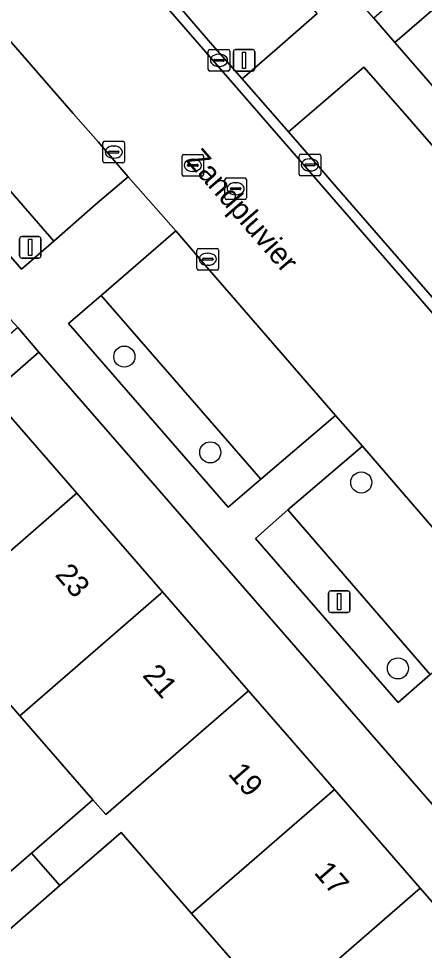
# Model space of a CAD drawing. Extents: x 155887 to 156869, y 383880 to 384678.
# Drawn here: x 156610.61 to 156629.4, y 384018.22 to 384061.4 of the extents above; entities that cross this region are included whole.
import ezdxf

# ---------------------------------------------------------------- set-up
doc = ezdxf.new("R2010")
doc.units = 0
for name, color, linetype in [('IMGEO_Berm_groen', 7, 'Continuous'), ('IMGEO_Boom', 7, 'Continuous'), ('IMGEO_Erf', 7, 'Continuous'), ('IMGEO_Kolk', 7, 'Continuous'), ('IMGEO_Lichtmast', 7, 'Continuous'), ('IMGEO_Openbare_ruimte_label', 7, 'Continuous'), ('IMGEO_Pand', 7, 'Continuous'), ('IMGEO_Pand_nummerreeks', 7, 'Continuous'), ('IMGEO_Parkeervlak_open', 7, 'Continuous'), ('IMGEO_Rijbaan_lokaal_gesloten', 7, 'Continuous'), ('IMGEO_Rijbaan_lokaal_open', 7, 'Continuous'), ('IMGEO_Rioolput', 7, 'Continuous'), ('IMGEO_Voetpad_open', 7, 'Continuous')]:
    doc.layers.add(name, color=color, linetype=linetype)

msp = doc.modelspace()

# ---------------------------------------------------------------- linework, layer by layer
at = {"layer": 'IMGEO_Berm_groen'}
for points in [[(156604.722, 384059.704), (156603.227, 384058.448), (156610.737, 384049.787), (156612.242, 384051.077), (156609.695, 384053.999)], [(156614.431, 384048.566), (156612.922, 384047.266), (156620.318, 384038.756), (156621.82, 384040.051)], [(156623.074, 384038.632), (156621.574, 384037.301), (156628.184, 384029.703), (156629.666, 384031.006)]]:
    msp.add_lwpolyline(points, close=True, dxfattribs=at)
at = {"layer": 'IMGEO_Boom'}
for centre in [(156615.503, 384045.734), (156619.481, 384041.297), (156626.475, 384039.902), (156628.172, 384031.286)]:
    msp.add_circle(centre, 0.489, dxfattribs=at)
at = {"layer": 'IMGEO_Erf'}
for points in [[(156646.204, 384043.928), (156642.223, 384048.506), (156638.243, 384053.084), (156634.262, 384057.662), (156630.286, 384062.235), (156628.032, 384060.288), (156663.829, 384019.095), (156666.095, 384021.051), (156662.126, 384025.616), (156658.145, 384030.194), (156654.165, 384034.772), (156650.184, 384039.35)], [(156611.545, 384045.94), (156609.299, 384043.999), (156613.295, 384039.404), (156617.274, 384034.828), (156621.253, 384030.252), (156625.232, 384025.676), (156629.21, 384021.101), (156633.189, 384016.525), (156637.168, 384011.949), (156641.147, 384007.374), (156645.116, 384002.809), (156647.359, 384004.761)]]:
    msp.add_lwpolyline(points, close=True, dxfattribs=at)
for points in [[(156608.366, 384020.267), (156611.204, 384022.731), (156614.042, 384025.196), (156610.665, 384029.085), (156607.487, 384032.745)], [(156621.909, 384016.138), (156618.616, 384019.93), (156615.353, 384023.687), (156612.515, 384021.222), (156609.677, 384018.757)]]:
    msp.add_lwpolyline(points, dxfattribs=at)
at = {"layer": 'IMGEO_Kolk'}
for p, q in [((156619.385, 384059.038), (156619.385, 384059.89)), ((156619.46, 384059.964), (156620.312, 384059.964)), ((156620.386, 384059.89), (156620.386, 384059.038)), ((156619.644, 384059.458), (156619.644, 384059.47)), ((156620.082, 384059.421), (156619.684, 384059.421)), ((156619.687, 384059.507), (156620.085, 384059.507)), ((156619.873, 384059.744), (156619.898, 384059.744)), ((156620.128, 384059.47), (156620.128, 384059.458)), ((156620.312, 384058.964), (156619.46, 384058.964)), ((156619.896, 384059.184), (156619.871, 384059.184)), ((156614.511, 384054.784), (156614.511, 384055.636)), ((156614.586, 384055.71), (156615.438, 384055.71)), ((156614.999, 384055.49), (156615.024, 384055.49)), ((156615.512, 384055.636), (156615.512, 384054.784)), ((156614.77, 384055.204), (156614.77, 384055.216)), ((156615.208, 384055.167), (156614.81, 384055.167)), ((156614.813, 384055.253), (156615.211, 384055.253)), ((156615.254, 384055.216), (156615.254, 384055.204)), ((156623.597, 384054.192), (156623.597, 384055.044)), ((156623.672, 384055.118), (156624.524, 384055.118)), ((156624.598, 384055.044), (156624.598, 384054.192)), ((156615.438, 384054.71), (156614.586, 384054.71)), ((156615.022, 384054.93), (156614.997, 384054.93)), ((156623.856, 384054.612), (156623.856, 384054.624)), ((156623.899, 384054.661), (156624.297, 384054.661)), ((156624.085, 384054.898), (156624.11, 384054.898)), ((156624.34, 384054.624), (156624.34, 384054.612)), ((156624.294, 384054.575), (156623.896, 384054.575)), ((156624.108, 384054.338), (156624.083, 384054.338)), ((156624.524, 384054.118), (156623.672, 384054.118)), ((156618.942, 384050.746), (156619.794, 384050.746)), ((156618.867, 384049.82), (156618.867, 384050.672)), ((156619.169, 384050.289), (156619.567, 384050.289)), ((156619.355, 384050.526), (156619.38, 384050.526)), ((156619.868, 384050.672), (156619.868, 384049.82)), ((156619.126, 384050.24), (156619.126, 384050.252)), ((156619.564, 384050.203), (156619.166, 384050.203)), ((156619.378, 384049.966), (156619.353, 384049.966)), ((156619.61, 384050.252), (156619.61, 384050.24)), ((156619.794, 384049.746), (156618.942, 384049.746))]:
    msp.add_line(p, q, dxfattribs=at)
for points in [[(156619.385, 384059.038), (156619.385, 384059.89)], [(156619.46, 384059.964), (156620.312, 384059.964)], [(156620.386, 384059.89), (156620.386, 384059.038)], [(156620.312, 384058.964), (156619.46, 384058.964)], [(156614.511, 384054.784), (156614.511, 384055.636)], [(156614.586, 384055.71), (156615.438, 384055.71)], [(156615.512, 384055.636), (156615.512, 384054.784)], [(156623.597, 384054.192), (156623.597, 384055.044)], [(156623.672, 384055.118), (156624.524, 384055.118)], [(156624.598, 384055.044), (156624.598, 384054.192)], [(156615.438, 384054.71), (156614.586, 384054.71)], [(156624.524, 384054.118), (156623.672, 384054.118)], [(156618.942, 384050.746), (156619.794, 384050.746)], [(156618.867, 384049.82), (156618.867, 384050.672)], [(156619.868, 384050.672), (156619.868, 384049.82)], [(156619.794, 384049.746), (156618.942, 384049.746)]]:
    msp.add_lwpolyline(points, dxfattribs=at)
for centre, radius, start, end in [((156619.462, 384059.888), 0.0765, 91.552, 178.448), ((156619.462, 384059.888), 0.0765, 91.552, 178.448), ((156620.31, 384059.888), 0.0765, 1.552, 88.448), ((156620.31, 384059.888), 0.0765, 1.552, 88.448), ((156619.684, 384059.467), 0.0403, 85.8775, 175.7526), ((156619.681, 384059.457), 0.0366, 178.938, 274.7102), ((156620.085, 384059.464), 0.043, 264.8664, 352.4533), ((156620.089, 384059.469), 0.0386, 1.7309, 96.639), ((156619.462, 384059.04), 0.0765, 181.552, 268.448), ((156619.462, 384059.04), 0.0765, 181.552, 268.448), ((156620.31, 384059.04), 0.0765, 271.552, 358.448), ((156620.31, 384059.04), 0.0765, 271.552, 358.448), ((156614.588, 384055.634), 0.0765, 91.552, 178.448), ((156614.588, 384055.634), 0.0765, 91.552, 178.448), ((156615.436, 384055.634), 0.0765, 1.552, 88.448), ((156615.436, 384055.634), 0.0765, 1.552, 88.448), ((156614.81, 384055.213), 0.0403, 85.8775, 175.7526), ((156614.807, 384055.203), 0.0366, 178.938, 274.7102), ((156615.211, 384055.21), 0.043, 264.8664, 352.4533), ((156615.215, 384055.215), 0.0386, 1.7309, 96.639), ((156623.674, 384055.042), 0.0765, 91.552, 178.448), ((156623.674, 384055.042), 0.0765, 91.552, 178.448), ((156624.522, 384055.042), 0.0765, 1.552, 88.448), ((156624.522, 384055.042), 0.0765, 1.552, 88.448), ((156614.588, 384054.786), 0.0765, 181.552, 268.448), ((156614.588, 384054.786), 0.0765, 181.552, 268.448), ((156615.436, 384054.786), 0.0765, 271.552, 358.448), ((156615.436, 384054.786), 0.0765, 271.552, 358.448), ((156623.896, 384054.621), 0.0403, 85.8775, 175.7526), ((156623.893, 384054.611), 0.0366, 178.938, 274.7102), ((156624.297, 384054.618), 0.043, 264.8664, 352.4533), ((156624.301, 384054.623), 0.0386, 1.7309, 96.639), ((156623.674, 384054.194), 0.0765, 181.552, 268.448), ((156623.674, 384054.194), 0.0765, 181.552, 268.448), ((156624.522, 384054.194), 0.0765, 271.552, 358.448), ((156624.522, 384054.194), 0.0765, 271.552, 358.448), ((156618.944, 384050.67), 0.0765, 91.552, 178.448), ((156618.944, 384050.67), 0.0765, 91.552, 178.448), ((156619.792, 384050.67), 0.0765, 1.552, 88.448), ((156619.792, 384050.67), 0.0765, 1.552, 88.448), ((156619.166, 384050.249), 0.0403, 85.8775, 175.7526), ((156619.571, 384050.251), 0.0386, 1.7309, 96.639), ((156619.163, 384050.239), 0.0366, 178.938, 274.7102), ((156619.567, 384050.246), 0.043, 264.8664, 352.4533), ((156618.944, 384049.822), 0.0765, 181.552, 268.448), ((156618.944, 384049.822), 0.0765, 181.552, 268.448), ((156619.792, 384049.822), 0.0765, 271.552, 358.448), ((156619.792, 384049.822), 0.0765, 271.552, 358.448)]:
    msp.add_arc(centre, radius, start, end, dxfattribs=at)
for centre, major_axis, ratio, start_param, end_param in [((156619.872, 384059.464), (-0.387, 0.002), 0.722429, 4.712389, 7.853982), ((156619.897, 384059.464), (-0.39, 0.002), 0.717154, 1.570796, 4.712389), ((156614.998, 384055.21), (-0.387, 0.002), 0.722429, 4.712389, 7.853982), ((156615.023, 384055.21), (-0.39, 0.002), 0.717154, 1.570796, 4.712389), ((156624.084, 384054.618), (-0.387, 0.002), 0.722429, 4.712389, 7.853982), ((156624.109, 384054.618), (-0.39, 0.002), 0.717154, 1.570796, 4.712389), ((156619.354, 384050.246), (-0.387, 0.002), 0.722429, 4.712389, 7.853982), ((156619.379, 384050.246), (-0.39, 0.002), 0.717154, 1.570796, 4.712389)]:
    msp.add_ellipse(centre, major_axis=major_axis, ratio=ratio, start_param=start_param, end_param=end_param, dxfattribs=at)
at = {"layer": 'IMGEO_Lichtmast'}
for p, q in [((156620.551, 384059.063), (156620.551, 384059.863)), ((156620.551, 384059.863), (156620.551, 384059.063)), ((156620.651, 384059.963), (156621.441, 384059.963)), ((156621.441, 384059.963), (156620.651, 384059.963)), ((156621.541, 384059.863), (156621.541, 384059.063)), ((156621.541, 384059.063), (156621.541, 384059.863)), ((156621.441, 384058.963), (156620.651, 384058.963)), ((156620.651, 384058.963), (156621.441, 384058.963)), ((156610.648, 384050.398), (156610.648, 384051.198)), ((156610.648, 384051.198), (156610.648, 384050.398)), ((156610.748, 384051.298), (156611.538, 384051.298)), ((156611.538, 384051.298), (156610.748, 384051.298)), ((156611.638, 384051.198), (156611.638, 384050.398)), ((156611.638, 384050.398), (156611.638, 384051.198)), ((156611.538, 384050.298), (156610.748, 384050.298)), ((156610.748, 384050.298), (156611.538, 384050.298)), ((156624.96, 384033.977), (156624.96, 384034.777)), ((156624.96, 384034.777), (156624.96, 384033.977)), ((156625.06, 384034.877), (156625.85, 384034.877)), ((156625.85, 384034.877), (156625.06, 384034.877)), ((156625.95, 384034.777), (156625.95, 384033.977)), ((156625.95, 384033.977), (156625.95, 384034.777)), ((156625.85, 384033.877), (156625.06, 384033.877)), ((156625.06, 384033.877), (156625.85, 384033.877))]:
    msp.add_line(p, q, dxfattribs=at)
for points in [[(156620.971, 384059.838), (156621.121, 384059.838), (156621.121, 384059.088), (156620.971, 384059.088), (156620.971, 384059.838)], [(156611.068, 384051.173), (156611.218, 384051.173), (156611.218, 384050.423), (156611.068, 384050.423), (156611.068, 384051.173)], [(156625.38, 384034.752), (156625.53, 384034.752), (156625.53, 384034.002), (156625.38, 384034.002), (156625.38, 384034.752)]]:
    msp.add_lwpolyline(points, dxfattribs=at)
for centre, start, end in [((156620.651, 384059.863), 90, 180), ((156620.651, 384059.863), 90, 180), ((156621.441, 384059.863), 0, 90), ((156621.441, 384059.863), 360, 90), ((156620.651, 384059.063), 180, 270), ((156620.651, 384059.063), 180, 270), ((156621.441, 384059.063), 270, 0), ((156621.441, 384059.063), 270, 0), ((156610.748, 384051.198), 90, 180), ((156610.748, 384051.198), 90, 180), ((156611.538, 384051.198), 0, 90), ((156611.538, 384051.198), 360, 90), ((156610.748, 384050.398), 180, 270), ((156610.748, 384050.398), 180, 270), ((156611.538, 384050.398), 270, 0), ((156611.538, 384050.398), 270, 0), ((156625.06, 384034.777), 90, 180), ((156625.06, 384034.777), 90, 180), ((156625.85, 384034.777), 0, 90), ((156625.85, 384034.777), 360, 90), ((156625.06, 384033.977), 180, 270), ((156625.06, 384033.977), 180, 270), ((156625.85, 384033.977), 270, 0), ((156625.85, 384033.977), 270, 0)]:
    msp.add_arc(centre, 0.1, start, end, dxfattribs=at)
at = {"layer": 'IMGEO_Pand'}
for points in [[(156613.205, 384039.325), (156613.295, 384039.404), (156609.299, 384043.999), (156602.674, 384038.239), (156606.176, 384034.255), (156606.689, 384033.664)], [(156617.196, 384034.76), (156617.274, 384034.828), (156613.295, 384039.404), (156613.205, 384039.325), (156606.689, 384033.664), (156606.176, 384034.255), (156603.337, 384031.79), (156604.648, 384030.28), (156607.487, 384032.745), (156610.665, 384029.085)], [(156621.253, 384030.252), (156617.274, 384034.828), (156617.196, 384034.76), (156610.665, 384029.085), (156614.042, 384025.196), (156614.64, 384024.508)], [(156625.232, 384025.676), (156621.253, 384030.252), (156614.64, 384024.508), (156614.042, 384025.196), (156611.204, 384022.731), (156612.515, 384021.222), (156615.353, 384023.687), (156618.616, 384019.93)], [(156629.21, 384021.101), (156625.232, 384025.676), (156618.616, 384019.93), (156621.909, 384016.138), (156622.592, 384015.351)], [(156612.515, 384021.222), (156611.204, 384022.731), (156608.366, 384020.267), (156608.964, 384019.578), (156609.677, 384018.757)], [(156633.189, 384016.525), (156629.21, 384021.101), (156622.592, 384015.351), (156621.909, 384016.138), (156619.07, 384013.673), (156620.382, 384012.163), (156623.22, 384014.628), (156626.568, 384010.773)]]:
    msp.add_lwpolyline(points, close=True, dxfattribs=at)
at = {"layer": 'IMGEO_Parkeervlak_open'}
for points in [[(156616.904, 384070.314), (156613.441, 384067.288), (156618.345, 384061.609), (156619.483, 384060.292), (156620.955, 384058.609), (156622.581, 384060.015), (156624.428, 384061.64), (156621.832, 384064.636)], [(156608.204, 384062.662), (156604.722, 384059.704), (156609.695, 384053.999), (156612.242, 384051.077), (156614.168, 384052.776), (156615.678, 384054.06), (156614.29, 384055.679), (156613.133, 384057.006)], [(156628.486, 384056.983), (156626.59, 384059.141), (156624.722, 384057.535), (156623.112, 384056.157), (156624.566, 384054.471), (156625.01, 384053.951), (156634.535, 384043.005), (156638.005, 384046.033)], [(156619.335, 384049.866), (156617.88, 384051.561), (156616.264, 384050.155), (156614.431, 384048.566), (156621.82, 384040.051), (156625.284, 384043.011)], [(156623.074, 384038.632), (156629.666, 384031.006), (156633.113, 384033.952), (156626.529, 384041.587)]]:
    msp.add_lwpolyline(points, close=True, dxfattribs=at)
at = {"layer": 'IMGEO_Rijbaan_lokaal_gesloten'}
msp.add_lwpolyline([(156646.454, 384028.54), (156584.127, 384100.331), (156579.597, 384096.394), (156579.244, 384096.079), (156582.931, 384091.822), (156583.811, 384090.821), (156585.156, 384089.249), (156586.193, 384088.05), (156591.142, 384082.341), (156592.38, 384080.913), (156599, 384073.239), (156600.266, 384071.831), (156606.948, 384064.118), (156608.204, 384062.662), (156613.133, 384057.006), (156614.29, 384055.679), (156615.678, 384054.06), (156617.88, 384051.561), (156619.335, 384049.866), (156625.284, 384043.011), (156626.529, 384041.587), (156633.113, 384033.952)], dxfattribs=at)
at = {"layer": 'IMGEO_Rijbaan_lokaal_open'}
msp.add_lwpolyline([(156634.535, 384043.005), (156625.01, 384053.951), (156624.566, 384054.471), (156623.112, 384056.157), (156620.955, 384058.609), (156619.483, 384060.292), (156618.345, 384061.609), (156613.441, 384067.288), (156612.193, 384068.739), (156610.506, 384070.683), (156605.598, 384076.349), (156604.336, 384077.785), (156597.706, 384085.44), (156596.453, 384086.892), (156594.77, 384088.811), (156591.404, 384092.681), (156590.413, 384093.818), (156589.043, 384095.382), (156588.18, 384096.392), (156584.474, 384100.632), (156584.127, 384100.331), (156646.454, 384028.54)], dxfattribs=at)
at = {"layer": 'IMGEO_Rioolput'}
for p, q in [((156618.248, 384055.097), (156619.1, 384055.097)), ((156618.173, 384054.171), (156618.173, 384055.023)), ((156618.432, 384054.591), (156618.432, 384054.603)), ((156618.475, 384054.64), (156618.873, 384054.64)), ((156618.661, 384054.877), (156618.686, 384054.877)), ((156618.916, 384054.603), (156618.916, 384054.591)), ((156619.174, 384055.023), (156619.174, 384054.171)), ((156618.87, 384054.554), (156618.472, 384054.554)), ((156618.684, 384054.317), (156618.659, 384054.317)), ((156619.1, 384054.097), (156618.248, 384054.097)), ((156620.157, 384053.087), (156620.157, 384053.939)), ((156620.232, 384054.013), (156621.084, 384054.013)), ((156620.645, 384053.793), (156620.67, 384053.793)), ((156621.158, 384053.939), (156621.158, 384053.087)), ((156620.416, 384053.507), (156620.416, 384053.519)), ((156620.854, 384053.47), (156620.456, 384053.47)), ((156620.459, 384053.556), (156620.857, 384053.556)), ((156620.9, 384053.519), (156620.9, 384053.507)), ((156621.084, 384053.013), (156620.232, 384053.013)), ((156620.668, 384053.233), (156620.643, 384053.233))]:
    msp.add_line(p, q, dxfattribs=at)
for points in [[(156618.248, 384055.097), (156619.1, 384055.097)], [(156618.173, 384054.171), (156618.173, 384055.023)], [(156619.174, 384055.023), (156619.174, 384054.171)], [(156619.1, 384054.097), (156618.248, 384054.097)], [(156620.157, 384053.087), (156620.157, 384053.939)], [(156620.232, 384054.013), (156621.084, 384054.013)], [(156621.158, 384053.939), (156621.158, 384053.087)], [(156621.084, 384053.013), (156620.232, 384053.013)]]:
    msp.add_lwpolyline(points, dxfattribs=at)
for centre, radius, start, end in [((156618.25, 384055.021), 0.0765, 91.552, 178.448), ((156618.25, 384055.021), 0.0765, 91.552, 178.448), ((156619.098, 384055.021), 0.0765, 1.552, 88.448), ((156619.098, 384055.021), 0.0765, 1.552, 88.448), ((156618.472, 384054.6), 0.0403, 85.8775, 175.7526), ((156618.877, 384054.602), 0.0386, 1.7309, 96.639), ((156618.25, 384054.173), 0.0765, 181.552, 268.448), ((156618.25, 384054.173), 0.0765, 181.552, 268.448), ((156618.469, 384054.59), 0.0366, 178.938, 274.7102), ((156618.873, 384054.597), 0.043, 264.8664, 352.4533), ((156619.098, 384054.173), 0.0765, 271.552, 358.448), ((156619.098, 384054.173), 0.0765, 271.552, 358.448), ((156620.234, 384053.937), 0.0765, 91.552, 178.448), ((156620.234, 384053.937), 0.0765, 91.552, 178.448), ((156621.082, 384053.937), 0.0765, 1.552, 88.448), ((156621.082, 384053.937), 0.0765, 1.552, 88.448), ((156620.456, 384053.516), 0.0403, 85.8775, 175.7526), ((156620.453, 384053.506), 0.0366, 178.938, 274.7102), ((156620.857, 384053.513), 0.043, 264.8664, 352.4533), ((156620.861, 384053.518), 0.0386, 1.7309, 96.639), ((156620.234, 384053.089), 0.0765, 181.552, 268.448), ((156620.234, 384053.089), 0.0765, 181.552, 268.448), ((156621.082, 384053.089), 0.0765, 271.552, 358.448), ((156621.082, 384053.089), 0.0765, 271.552, 358.448)]:
    msp.add_arc(centre, radius, start, end, dxfattribs=at)
for centre, major_axis, ratio, start_param, end_param in [((156618.66, 384054.597), (-0.387, 0.002), 0.722429, 4.712389, 7.853982), ((156618.685, 384054.597), (-0.39, 0.002), 0.717154, 1.570796, 4.712389), ((156620.644, 384053.513), (-0.387, 0.002), 0.722429, 4.712389, 7.853982), ((156620.669, 384053.513), (-0.39, 0.002), 0.717154, 1.570796, 4.712389)]:
    msp.add_ellipse(centre, major_axis=major_axis, ratio=ratio, start_param=start_param, end_param=end_param, dxfattribs=at)
at = {"layer": 'IMGEO_Voetpad_open'}
for points in [[(156628.032, 384060.288), (156627.051, 384061.422), (156626.735, 384061.795), (156625.75, 384062.919), (156593.911, 384099.613), (156593.045, 384100.611), (156589.344, 384104.881), (156587.667, 384106.816), (156583.03, 384102.742)], [(156577.111, 384097.787), (156571.128, 384092.444), (156572.838, 384090.477), (156576.501, 384086.263), (156577.371, 384085.262), (156609.255, 384048.581), (156610.251, 384047.438), (156610.564, 384047.077), (156611.545, 384045.94), (156647.359, 384004.761)], [(156616.264, 384050.155), (156617.88, 384051.561), (156615.678, 384054.06), (156614.168, 384052.776), (156612.242, 384051.077), (156610.737, 384049.787), (156603.227, 384058.448), (156604.722, 384059.704), (156608.204, 384062.662)], [(156624.428, 384061.64), (156622.581, 384060.015), (156620.955, 384058.609), (156623.112, 384056.157), (156624.722, 384057.535), (156626.59, 384059.141), (156628.486, 384056.983), (156638.005, 384046.033)], [(156663.829, 384019.095), (156628.032, 384060.288)], [(156629.666, 384031.006), (156628.184, 384029.703), (156621.574, 384037.301), (156623.074, 384038.632), (156626.529, 384041.587), (156625.284, 384043.011), (156621.82, 384040.051), (156620.318, 384038.756), (156612.922, 384047.266), (156614.431, 384048.566), (156616.264, 384050.155)]]:
    msp.add_lwpolyline(points, dxfattribs=at)
for points in [[(156636.922, 384067.987), (156645.025, 384075.023), (156646.945, 384076.691), (156658.559, 384086.776), (156665.791, 384093.061), (156666.669, 384093.809), (156665.67, 384094.951), (156627.051, 384061.422), (156628.032, 384060.288), (156630.286, 384062.235)], [(156611.545, 384045.94), (156610.564, 384047.077), (156571.955, 384013.575), (156572.933, 384012.431), (156573.798, 384013.184), (156583.457, 384021.55), (156592.56, 384029.456), (156594.535, 384031.171), (156602.674, 384038.239), (156609.299, 384043.999)]]:
    msp.add_lwpolyline(points, close=True, dxfattribs=at)

# ---------------------------------------------------------------- texts
at = {"layer": 'IMGEO_Openbare_ruimte_label'}
msp.add_text('Zandpluvier', height=1, rotation=310.9433, dxfattribs=at).set_placement((156618.311, 384054.829))
at = {"layer": 'IMGEO_Pand_nummerreeks'}
for s, p in [('23', (156612.252, 384035.606)), ('21', (156616.306, 384030.943)), ('19', (156620.27, 384026.384)), ('17', (156624.25, 384021.807))]:
    msp.add_text(s, height=1, rotation=311.0064, dxfattribs=at).set_placement(p)

doc.saveas('drawing.dxf')
